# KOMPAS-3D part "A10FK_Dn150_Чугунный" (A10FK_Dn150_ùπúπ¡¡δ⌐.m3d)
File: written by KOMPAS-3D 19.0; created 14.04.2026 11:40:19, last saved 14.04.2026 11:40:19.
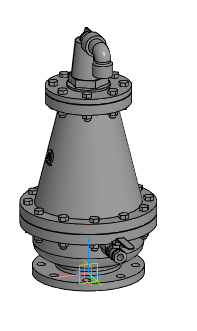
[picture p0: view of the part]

Document properties: Автор: Энергия; Полное имя файла: Z:\3.Личные\kachalov\3d для проектировщиков\x.x Тип A10FK Двухступенчатый воздухоотводчик\stp_Тип A10FK Двухступенчатый воздухоотводчик\A10FK_Dn150_Чугунный.m3d

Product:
- Part/product: A10FK_Dn150_Чугунный

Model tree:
1. Операция без истории:1  (labels: A10FK_Dn150_Чугунный)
